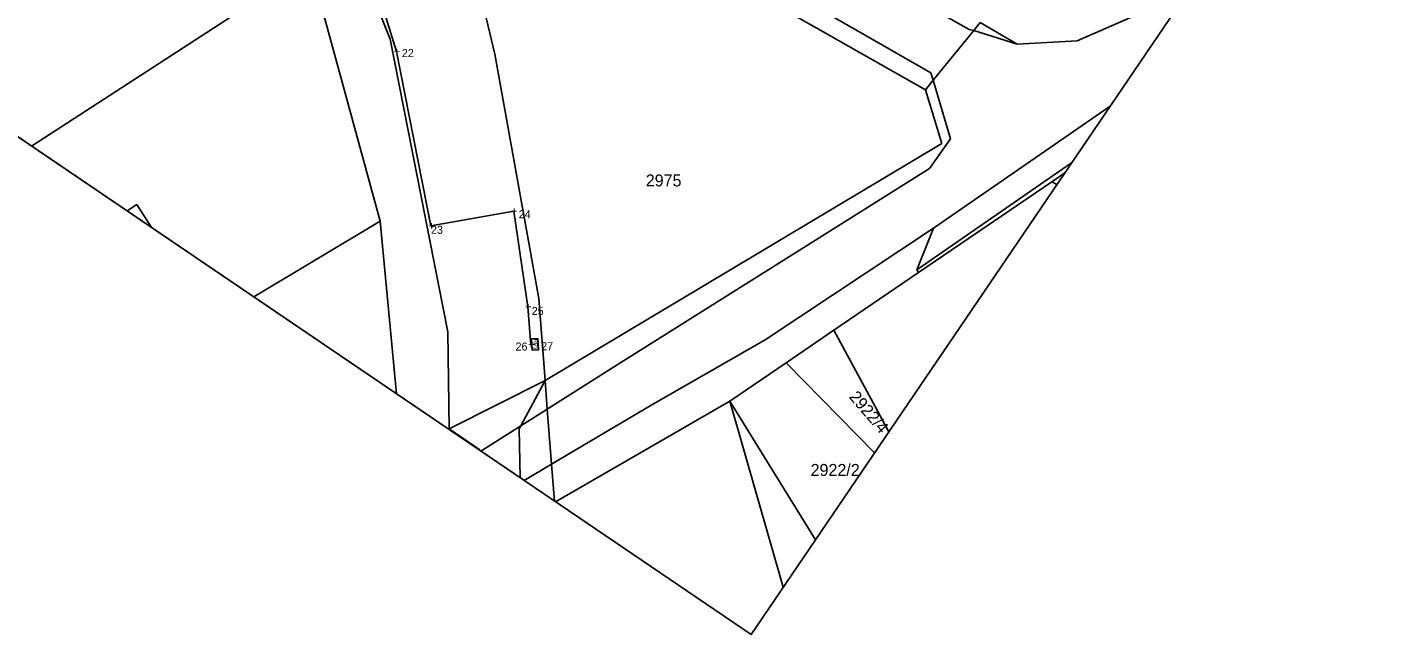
# Model space of a CAD drawing. Extents: x -620450 to -619936, y -1122925 to -1122443.
# Drawn here: x -620193.1 to -620022.1, y -1122924.7 to -1122848.8 of the extents above; entities that cross this region are included whole.
import ezdxf

# ---------------------------------------------------------------- set-up
doc = ezdxf.new("R2010")
doc.units = 0
for name, color, linetype in [('060603_ROZVODY_NN', 7, 'Continuous'), ('BODY', 7, 'Continuous'), ('BODY POPIS', 7, 'Continuous'), ('RÁMY', 7, 'Continuous'), ('Vrstva 53', 7, 'Continuous'), ('Vrstva 55', 7, 'Continuous'), ('Vrstva 56', 7, 'Continuous'), ('Vrstva 57', 7, 'Continuous')]:
    doc.layers.add(name, color=color, linetype=linetype)

msp = doc.modelspace()

# ---------------------------------------------------------------- linework, layer by layer
at = {"layer": '060603_ROZVODY_NN'}
msp.add_lwpolyline([(-620240.17, -1122718.34), (-620228.34, -1122728.07), (-620221.17, -1122735.76), (-620213.63, -1122742.04), (-620205.95, -1122748.19), (-620177.51, -1122774.52), (-620185.52, -1122781.05), (-620181.59, -1122785.57), (-620173.13, -1122796.4), (-620158.91, -1122820.61), (-620151.64, -1122838.53), (-620148.85, -1122845.74), (-620146.97, -1122851.79), (-620142.65, -1122873.56), (-620132.31, -1122871.72), (-620130.54, -1122883.68), (-620130.19, -1122888.41), (-620130.04, -1122888.39)], dxfattribs=at)
msp.add_lwpolyline([(-620129.29, -1122887.64), (-620129.22, -1122889.07), (-620130, -1122889.11), (-620130.07, -1122887.68)], close=True, dxfattribs=at)
at = {"layer": 'RÁMY'}
for points in [[(-620366.66, -1122565.85), (-620019.21, -1122801.81), (-620102.64, -1122924.66), (-620450.09, -1122688.7)], [(-620279.8, -1122624.84), (-620019.21, -1122801.81), (-620102.64, -1122924.66), (-620363.23, -1122747.69)]]:
    msp.add_lwpolyline(points, close=True, dxfattribs=at)
at = {"layer": 'Vrstva 53'}
for p, q in [((-620143.18, -1122816.17), (-620134.66, -1122852.11)), ((-620147.76, -1122850.22), (-620152.84, -1122837.4))]:
    msp.add_line(p, q, dxfattribs=at)
at = {"layer": 'Vrstva 55'}
for p, q in [((-620134.66, -1122852.11), (-620143.18, -1122816.17)), ((-620080.86, -1122856.55), (-620132.47, -1122827.27)), ((-620152.84, -1122837.4), (-620147.76, -1122850.22)), ((-620157.72, -1122840.99), (-620192.57, -1122863.59)), ((-620061.9, -1122850.43), (-620053.99, -1122846.97)), ((-620074.02, -1122848.16), (-620074.83, -1122849.15)), ((-620074.02, -1122848.16), (-620069.41, -1122850.86)), ((-620147.76, -1122850.22), (-620140.56, -1122886.8)), ((-620074.83, -1122849.15), (-620079.9, -1122855.37)), ((-620069.41, -1122850.86), (-620061.9, -1122850.43)), ((-620129.18, -1122882.66), (-620134.66, -1122852.11)), ((-620079.9, -1122855.37), (-620080.86, -1122856.55)), ((-620078.79, -1122863.28), (-620080.86, -1122856.55)), ((-620064.79, -1122863.44), (-620057.78, -1122858.61)), ((-620128.4, -1122892.9), (-620078.79, -1122863.28)), ((-620079.86, -1122873.87), (-620064.79, -1122863.44)), ((-620063.45, -1122866.95), (-620065.08, -1122868.06)), ((-620065.08, -1122868.06), (-620081.71, -1122879.39)), ((-620064.42, -1122868.38), (-620065.08, -1122868.06)), ((-620180.63, -1122871.7), (-620179.4, -1122870.92)), ((-620179.4, -1122870.92), (-620177.6, -1122873.76)), ((-620164.8, -1122882.45), (-620149.02, -1122872.99)), ((-620149.02, -1122872.99), (-620146.95, -1122894.57)), ((-620081.95, -1122879.05), (-620079.86, -1122873.87)), ((-620081.71, -1122879.39), (-620092.29, -1122886.6)), ((-620081.71, -1122879.39), (-620081.95, -1122879.05)), ((-620128.4, -1122892.9), (-620129.18, -1122882.66)), ((-620140.56, -1122886.8), (-620140.38, -1122898.92)), ((-620092.29, -1122886.6), (-620098.27, -1122890.68)), ((-620085.42, -1122899.31), (-620092.29, -1122886.6)), ((-620098.27, -1122890.68), (-620105.32, -1122895.5)), ((-620087.22, -1122901.95), (-620098.27, -1122890.68)), ((-620140.38, -1122898.92), (-620128.4, -1122892.9)), ((-620131.42, -1122898.55), (-620128.4, -1122892.9)), ((-620105.32, -1122895.5), (-620127.1, -1122908.05)), ((-620094.59, -1122912.81), (-620105.32, -1122895.5)), ((-620105.32, -1122895.5), (-620098.62, -1122918.74)), ((-620140.38, -1122898.92), (-620140.46, -1122898.98)), ((-620140.38, -1122898.92), (-620136.53, -1122901.57)), ((-620131.63, -1122898.95), (-620131.42, -1122898.55)), ((-620131.52, -1122905.05), (-620131.63, -1122898.95)), ((-620136.53, -1122901.57), (-620136.53, -1122901.65))]:
    msp.add_line(p, q, dxfattribs=at)
at = {"layer": 'Vrstva 56'}
for p, q in [((-620127.92, -1122819.29), (-620075.39, -1122849.03)), ((-620149.02, -1122872.99), (-620157.72, -1122840.99)), ((-620104.21, -1122840.64), (-620080.18, -1122854.43)), ((-620075.39, -1122849.03), (-620074.83, -1122849.15)), ((-620074.83, -1122849.15), (-620069.41, -1122850.86)), ((-620080.18, -1122854.43), (-620079.9, -1122855.37)), ((-620079.9, -1122855.37), (-620077.73, -1122862.7)), ((-620077.73, -1122862.7), (-620080.37, -1122866.39)), ((-620062.6, -1122865.7), (-620081.95, -1122879.05)), ((-620080.37, -1122866.39), (-620119.37, -1122890.92)), ((-620100.87, -1122887.82), (-620079.86, -1122873.87)), ((-620100.87, -1122887.82), (-620115.07, -1122895.95)), ((-620119.37, -1122890.92), (-620128.12, -1122896.46)), ((-620128.4, -1122892.9), (-620128.12, -1122896.46)), ((-620128.12, -1122896.46), (-620131.42, -1122898.55)), ((-620128.12, -1122896.46), (-620127.59, -1122903.37)), ((-620115.07, -1122895.95), (-620127.59, -1122903.37)), ((-620140.38, -1122898.92), (-620140.37, -1122899.04)), ((-620131.42, -1122898.55), (-620136.42, -1122901.72)), ((-620127.59, -1122903.37), (-620131.01, -1122905.4)), ((-620127.59, -1122903.37), (-620127.23, -1122907.96))]:
    msp.add_line(p, q, dxfattribs=at)

# ---------------------------------------------------------------- texts
at = {"layer": '060603_ROZVODY_NN'}
msp.add_text('RP1', height=0.5, rotation=272.8435, dxfattribs=at).set_placement((-620129.88, -1122887.72))
at = {"layer": 'BODY'}
for p in [(-620147.3, -1122852.29), (-620132.65, -1122872.22), (-620142.98, -1122874.06), (-620130.88, -1122884.18), (-620130.37, -1122888.89), (-620130.53, -1122888.91)]:
    msp.add_text('+', height=1, dxfattribs=at).set_placement(p)
at = {"layer": 'BODY POPIS'}
for s, p in [('22', (-620146.29, -1122852.47)), ('24', (-620131.68, -1122872.61)), ('23', (-620142.65, -1122874.56)), ('25', (-620130.06, -1122884.7)), ('26', (-620132.08, -1122889.15)), ('27', (-620128.88, -1122889.11))]:
    msp.add_text(s, height=1, dxfattribs=at).set_placement(p)
at = {"layer": 'Vrstva 57'}
for s, p in [('2975', (-620115.81, -1122868.64)), ('2922/2', (-620095.21, -1122904.83))]:
    msp.add_text(s, height=1.5, dxfattribs=at).set_placement(p)
msp.add_text('2922/4', height=1.5, rotation=310.6923, dxfattribs=at).set_placement((-620090.49, -1122894.99))

doc.saveas('drawing.dxf')
